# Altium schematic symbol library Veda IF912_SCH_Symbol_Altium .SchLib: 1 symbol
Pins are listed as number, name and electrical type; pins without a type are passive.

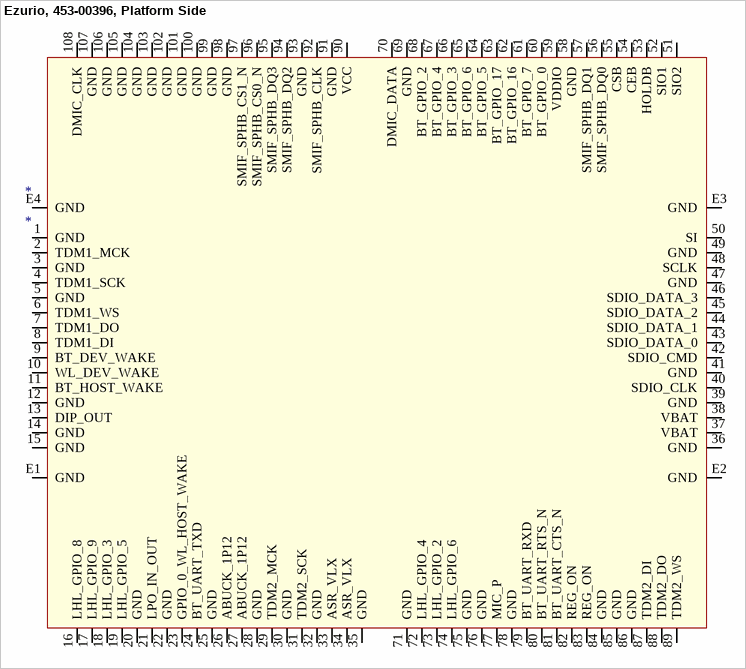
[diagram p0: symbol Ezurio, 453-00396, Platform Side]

## Ezurio, 453-00396, Platform Side
designator *
MOD, Veda IF912, SIP, Dual Band, No Embedded Memory, RF Trace Pin
pins: 1 GND, 2 TDM1_MCK, 3 GND, 4 TDM1_SCK, 5 GND, 6 TDM1_WS, 7 TDM1_DO, 8 TDM1_DI, 9 BT_DEV_WAKE, 10 WL_DEV_WAKE, 11 BT_HOST_WAKE, 12 GND, 13 DIP_OUT, 14 GND, 15 GND, 16 LHL_GPIO_8, 17 LHL_GPIO_9, 18 LHL_GPIO_3, 19 LHL_GPIO_5, 20 GND, 21 LPO_IN_OUT, 22 GND, 23 GPIO_0_WL_HOST_WAKE, 24 BT_UART_TXD, 25 GND, 26 ABUCK_1P12, 27 ABUCK_1P12, 28 GND, 29 TDM2_MCK, 30 GND, 31 TDM2_SCK, 32 GND, 33 ASR_VLX, 34 ASR_VLX, 35 GND, 36 GND, 37 VBAT, 38 VBAT, 39 GND, 40 SDIO_CLK, 41 GND, 42 SDIO_CMD, 43 SDIO_DATA_0, 44 SDIO_DATA_1, 45 SDIO_DATA_2, 46 SDIO_DATA_3, 47 GND, 48 SCLK, 49 GND, 50 SI, 51 SIO2, 52 SIO1, 53 HOLDB, 54 CEB, 55 CSB, 56 SMIF_SPHB_DQ0, 57 SMIF_SPHB_DQ1, 58 GND, 59 VDDIO, 60 BT_GPIO_0, 61 BT_GPIO_7, 62 BT_GPIO_16, 63 BT_GPIO_17, 64 BT_GPIO_5, 65 BT_GPIO_6, 66 BT_GPIO_3, 67 BT_GPIO_4, 68 BT_GPIO_2, 69 GND, 70 DMIC_DATA, 71 GND, 72 LHL_GPIO_4, 73 LHL_GPIO_2, 74 LHL_GPIO_6, 75 GND, 76 GND, 77 MIC_P, 78 GND, 79 BT_UART_RXD, 80 BT_UART_RTS_N, 81 BT_UART_CTS_N, 82 REG_ON, 83 REG_ON, 84 GND, 85 GND, 86 GND, 87 TDM2_DI, 88 TDM2_DO, 89 TDM2_WS, 90 VCC, 91 GND, 92 SMIF_SPHB_CLK, 93 GND, 94 SMIF_SPHB_DQ2, 95 SMIF_SPHB_DQ3, 96 SMIF_SPHB_CS0_N, 97 SMIF_SPHB_CS1_N, 98 GND, 99 GND, 100 GND, 101 GND, 102 GND, 103 GND, 104 GND, 105 GND, 106 GND, 107 GND, 108 DMIC_CLK, E1 GND, E2 GND, E3 GND, E4 GND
